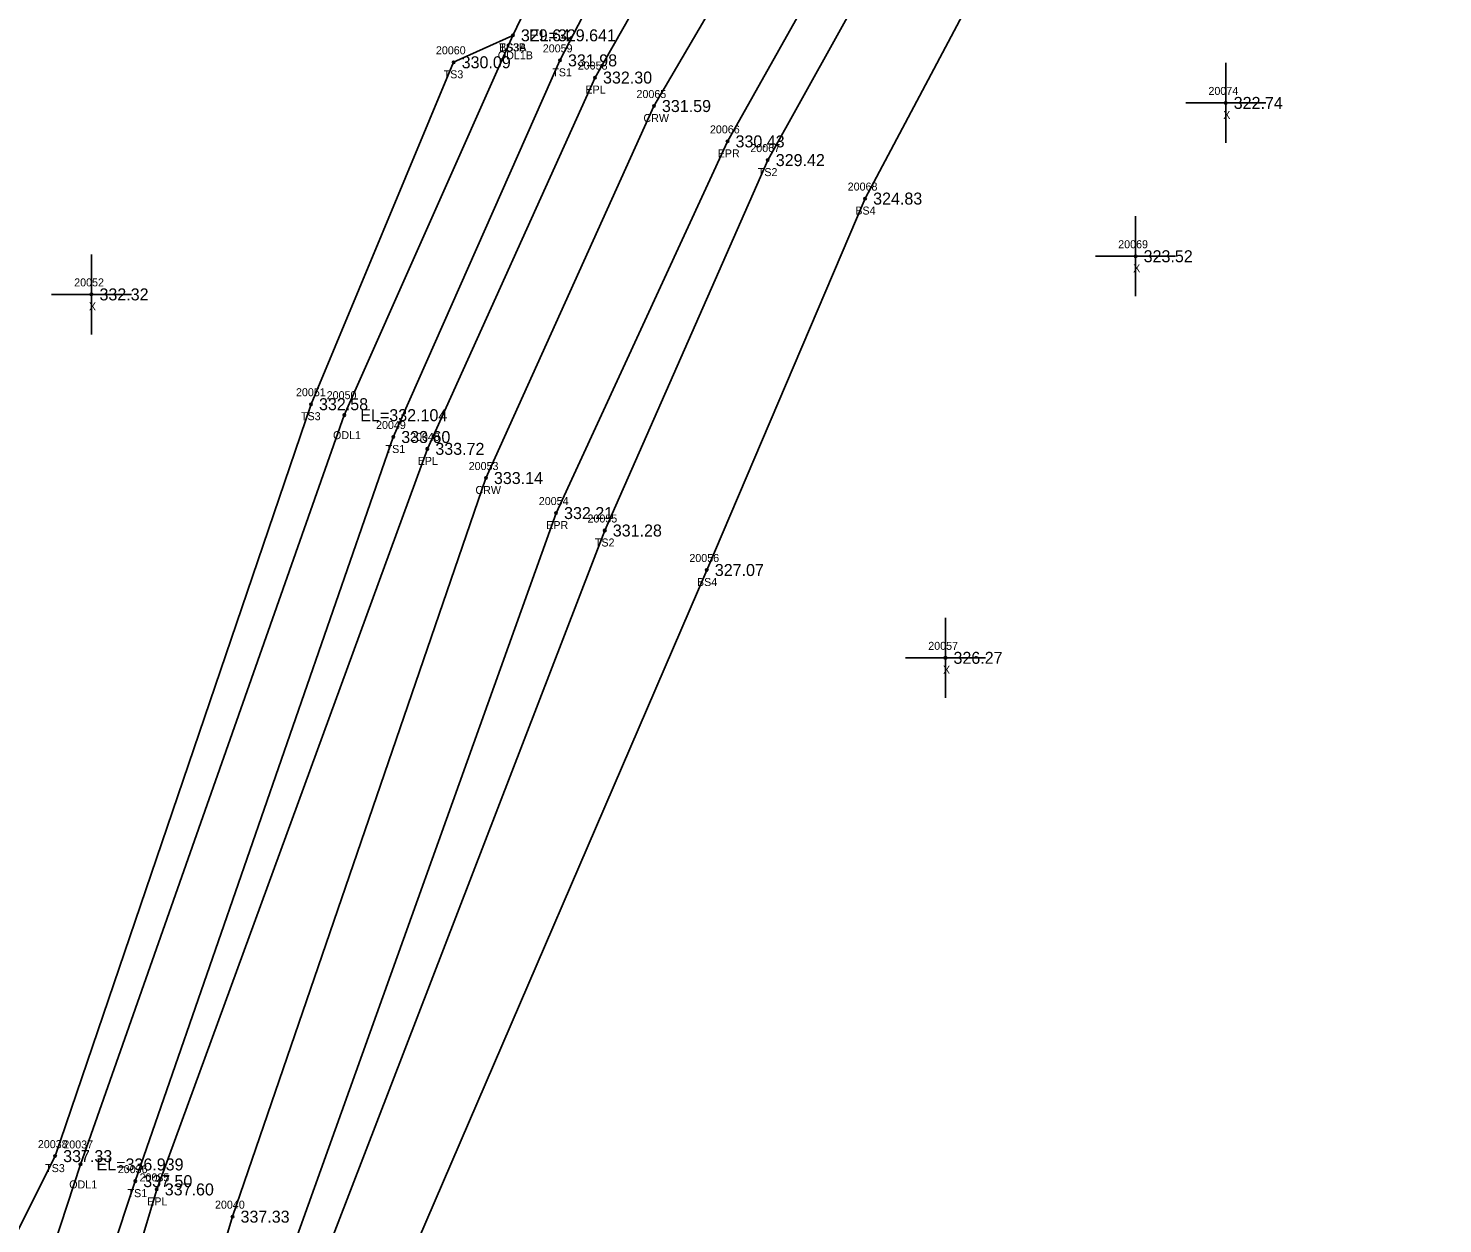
# Model space of a CAD drawing. Extents: x 2231109 to 2232328, y 1035718 to 1036919.
# Drawn here: x 2231228.7 to 2231405.5, y 1036036.4 to 1036185.9 of the extents above; entities that cross this region are included whole.
import ezdxf

# ---------------------------------------------------------------- set-up
doc = ezdxf.new("R2010")
doc.units = 0
for name, color, linetype in [('RD_DTM_BkLn1', 7, 'Continuous'), ('RD_DTM_BkLn2', 7, 'Continuous'), ('RD_DTM_BkLn_txCode', 7, 'Continuous'), ('RD_EX_H2O', 7, 'Continuous'), ('RD_EX_H2O_txCode', 7, 'Continuous'), ('RD_EX_Misc', 7, 'Continuous'), ('RD_EX_Misc_txCode', 7, 'Continuous'), ('RD_EX_Road', 7, 'Continuous'), ('RD_EX_Road_txCode', 7, 'Continuous'), ('RD_EX_TX_H2O_ELEV', 7, 'Continuous'), ('RD_EX_TX_Misc_ELEV', 7, 'Continuous'), ('RD_EX_TX_Road_ELEV', 7, 'Continuous'), ('RD_HC_Survey_ELEV', 7, 'Continuous'), ('RD_HC_Survey_txCode', 7, 'Continuous'), ('RD_SMD_Locator', 7, 'Continuous')]:
    doc.layers.add(name, color=color, linetype=linetype)

msp = doc.modelspace()

# ---------------------------------------------------------------- linework, layer by layer
at = {"layer": 'RD_DTM_BkLn1'}
msp.add_lwpolyline([(2231168.25, 1035745.18), (2231197.3, 1035848.59), (2231226.32, 1035944.04), (2231254.24, 1036037.31), (2231285.91, 1036129.66), (2231306.91, 1036176.17), (2231330.56, 1036216.58), (2231356.95, 1036257.36), (2231387.54, 1036294.26), (2231422.35, 1036330.42), (2231422.35, 1036330.4), (2231458.4, 1036362.33), (2231503.71, 1036399.67), (2231541.46, 1036424.96)], dxfattribs=at)
at = {"layer": 'RD_DTM_BkLn2'}
for points in [[(2231289.28, 1036185.01), (2231310.58, 1036229.41), (2231341.66, 1036269.31), (2231367.87, 1036310.22), (2231401.74, 1036350.83), (2231444.02, 1036383.07), (2231489.16, 1036422.11), (2231530.24, 1036446.93), (2231543.7, 1036441.83)], [(2231153.91, 1035749.54), (2231183.9, 1035852.41), (2231210.94, 1035948.08), (2231242.08, 1036041.75), (2231274.33, 1036134.79), (2231295.17, 1036181.88), (2231317.55, 1036225.12), (2231346.22, 1036265.16), (2231373.72, 1036304.6), (2231409.94, 1036342.78), (2231447.25, 1036376.56), (2231493.69, 1036413.26), (2231528.08, 1036438.61), (2231532.84, 1036438.24), (2231534.71, 1036436.33)], [(2231276.31, 1036031.77), (2231313.52, 1036118.16), (2231333.31, 1036164.6), (2231353.04, 1036201.77), (2231379.52, 1036238.63), (2231408.34, 1036274.21), (2231439.77, 1036308.83), (2231482.36, 1036339.48), (2231523.58, 1036374.84), (2231550.15, 1036393.87), (2231557.23, 1036405.65), (2231555.87, 1036413.6)], [(2231180.99, 1035741.83), (2231209.96, 1035844.49), (2231237.45, 1035939.8), (2231265.71, 1036032.03), (2231300.77, 1036123.1), (2231321.14, 1036169.41), (2231342.59, 1036208.04), (2231368.53, 1036247.79), (2231397.69, 1036285.75), (2231431.64, 1036319.41), (2231468.01, 1036352.78), (2231515.06, 1036385.58), (2231547.14, 1036404.2), (2231548.89, 1036408.2), (2231548.45, 1036412.54)], [(2231138.42, 1035755.04), (2231160.04, 1035859.88), (2231169.24, 1035891.81), (2231170.96, 1035897.04), (2231186.09, 1035952.96), (2231232.07, 1036044.88), (2231264.05, 1036138.89), (2231281.88, 1036181.64), (2231289.28, 1036185.01)]]:
    msp.add_lwpolyline(points, dxfattribs=at)
at = {"layer": 'RD_EX_H2O'}
msp.add_lwpolyline([(2231149.43, 1035751.43), (2231176.95, 1035854.91), (2231204.32, 1035949.66), (2231235.24, 1036043.84), (2231268.21, 1036137.52), (2231289.28, 1036185.01)], dxfattribs=at)
at = {"layer": 'RD_EX_Misc'}
for p, q in [((2231378.38, 1036171.56), (2231378.38, 1036181.56)), ((2231373.38, 1036176.56), (2231383.38, 1036176.56)), ((2231367.12, 1036152.39), (2231367.12, 1036162.39)), ((2231236.61, 1036147.62), (2231236.61, 1036157.62)), ((2231362.12, 1036157.39), (2231372.12, 1036157.39)), ((2231231.61, 1036152.62), (2231241.61, 1036152.62)), ((2231343.35, 1036102.18), (2231343.35, 1036112.18)), ((2231338.35, 1036107.18), (2231348.35, 1036107.18))]:
    msp.add_line(p, q, dxfattribs=at)
at = {"layer": 'RD_EX_Road'}
for points in [[(2231158.42, 1035748.11), (2231188.37, 1035851.38), (2231216.59, 1035946.92), (2231244.77, 1036040.72), (2231278.59, 1036133.31), (2231299.55, 1036179.73), (2231323.11, 1036221.2), (2231350.7, 1036262.3), (2231381.59, 1036299.29), (2231415.97, 1036336.9), (2231452.94, 1036369.74), (2231498.19, 1036405.3), (2231537.2, 1036432.57), (2231541.46, 1036424.96)], [(2231176.43, 1035742.89), (2231206.61, 1035845.83), (2231234.19, 1035940.65), (2231261.92, 1036033.75), (2231294.68, 1036125.28), (2231316.11, 1036171.75), (2231338.19, 1036211.09), (2231363.83, 1036252.38), (2231394.08, 1036289.28), (2231427.67, 1036324.2), (2231464.37, 1036355.5), (2231508.96, 1036392.41), (2231546.55, 1036416.22), (2231541.46, 1036424.96)]]:
    msp.add_lwpolyline(points, dxfattribs=at)
at = {"layer": 'RD_SMD_Locator'}
for centre in [(2231289.28, 1036185.01), (2231289.28, 1036185.01), (2231289.28, 1036185.01), (2231281.88, 1036181.64), (2231295.17, 1036181.88), (2231299.55, 1036179.73), (2231306.91, 1036176.17), (2231378.38, 1036176.56), (2231316.11, 1036171.75), (2231321.14, 1036169.41), (2231333.31, 1036164.6), (2231367.12, 1036157.39), (2231236.61, 1036152.62), (2231264.05, 1036138.89), (2231268.21, 1036137.52), (2231274.33, 1036134.79), (2231278.59, 1036133.31), (2231285.91, 1036129.66), (2231294.68, 1036125.28), (2231300.77, 1036123.1), (2231313.52, 1036118.16), (2231343.35, 1036107.18), (2231232.07, 1036044.88), (2231235.24, 1036043.84), (2231242.08, 1036041.75), (2231244.77, 1036040.72), (2231254.24, 1036037.31)]:
    msp.add_circle(centre, 0.15, dxfattribs=at)

# ---------------------------------------------------------------- texts
at = {"layer": 'RD_DTM_BkLn_txCode'}
for s, p in [('20060', (2231279.66, 1036182.64)), ('TS3B', (2231287.57, 1036183.01)), ('BS3A', (2231287.57, 1036183.01)), ('20059', (2231293.02, 1036182.88)), ('TS3', (2231280.63, 1036179.64)), ('TS1', (2231294.21, 1036179.88)), ('20067', (2231318.96, 1036170.41)), ('TS2', (2231319.89, 1036167.41)), ('20068', (2231331.13, 1036165.6)), ('BS4', (2231332.08, 1036162.6)), ('20051', (2231262.17, 1036139.89)), ('TS3', (2231262.8, 1036136.89)), ('20049', (2231272.18, 1036135.79)), ('TS1', (2231273.37, 1036132.79)), ('20055', (2231298.61, 1036124.1)), ('TS2', (2231299.53, 1036121.1)), ('20056', (2231311.34, 1036119.16)), ('BS4', (2231312.29, 1036116.16)), ('20038', (2231229.91, 1036045.88)), ('TS3', (2231230.82, 1036042.88)), ('20036', (2231239.9, 1036042.75)), ('TS1', (2231241.12, 1036039.75))]:
    msp.add_text(s, height=1, dxfattribs=at).set_placement(p)
at = {"layer": 'RD_EX_H2O_txCode'}
for s, p in [('ODL1B', (2231287.4, 1036182.01)), ('20050', (2231266.01, 1036139.52)), ('ODL1', (2231266.8, 1036134.52)), ('20037', (2231233.09, 1036045.84)), ('ODL1', (2231233.83, 1036040.84))]:
    msp.add_text(s, height=1, dxfattribs=at).set_placement(p)
at = {"layer": 'RD_EX_Misc_txCode'}
for s, p in [('20074', (2231376.22, 1036177.56)), ('X', (2231378.07, 1036174.56)), ('20069', (2231364.94, 1036158.39)), ('X', (2231366.81, 1036155.39)), ('20052', (2231234.45, 1036153.62)), ('X', (2231236.29, 1036150.62)), ('20057', (2231341.2, 1036108.18)), ('X', (2231343.04, 1036105.18))]:
    msp.add_text(s, height=1, dxfattribs=at).set_placement(p)
at = {"layer": 'RD_EX_Road_txCode'}
for s, p in [('20058', (2231297.39, 1036180.73)), ('EPL', (2231298.35, 1036177.73)), ('20066', (2231313.91, 1036172.75)), ('EPR', (2231314.88, 1036169.75)), ('20048', (2231276.43, 1036134.31)), ('EPL', (2231277.38, 1036131.31)), ('20054', (2231292.52, 1036126.28)), ('EPR', (2231293.45, 1036123.28)), ('20035', (2231242.62, 1036041.72)), ('EPL', (2231243.57, 1036038.72))]:
    msp.add_text(s, height=1, dxfattribs=at).set_placement(p)
at = {"layer": 'RD_EX_TX_H2O_ELEV'}
for s, p in [('EL=329.641', (2231291.28, 1036184.26)), ('EL=332.104', (2231270.21, 1036136.77)), ('EL=336.939', (2231237.24, 1036043.09))]:
    msp.add_text(s, height=1.5, dxfattribs=at).set_placement(p)
at = {"layer": 'RD_EX_TX_Misc_ELEV'}
for s, p in [('329.64', (2231290.28, 1036184.26)), ('329.64', (2231290.28, 1036184.26)), ('330.09', (2231282.88, 1036180.89)), ('331.98', (2231296.17, 1036181.13)), ('322.74', (2231379.38, 1036175.81)), ('329.42', (2231322.14, 1036168.66)), ('324.83', (2231334.31, 1036163.85)), ('323.52', (2231368.12, 1036156.64)), ('332.32', (2231237.61, 1036151.87)), ('332.58', (2231265.05, 1036138.14)), ('333.60', (2231275.33, 1036134.04)), ('331.28', (2231301.77, 1036122.35)), ('327.07', (2231314.52, 1036117.41)), ('326.27', (2231344.35, 1036106.43)), ('337.33', (2231233.07, 1036044.13)), ('337.50', (2231243.08, 1036041))]:
    msp.add_text(s, height=1.5, dxfattribs=at).set_placement(p)
at = {"layer": 'RD_EX_TX_Road_ELEV'}
for s, p in [('332.30', (2231300.55, 1036178.98)), ('330.43', (2231317.11, 1036171)), ('333.72', (2231279.59, 1036132.56)), ('332.21', (2231295.68, 1036124.53)), ('337.60', (2231245.77, 1036039.97))]:
    msp.add_text(s, height=1.5, dxfattribs=at).set_placement(p)
at = {"layer": 'RD_HC_Survey_ELEV'}
for s, p in [('331.59', (2231307.91, 1036175.42)), ('333.14', (2231286.91, 1036128.91)), ('337.33', (2231255.24, 1036036.56))]:
    msp.add_text(s, height=1.5, dxfattribs=at).set_placement(p)
at = {"layer": 'RD_HC_Survey_txCode'}
for s, p in [('20065', (2231304.73, 1036177.17)), ('CRW', (2231305.6, 1036174.17)), ('20053', (2231283.76, 1036130.66)), ('CRW', (2231284.6, 1036127.66)), ('20040', (2231252.05, 1036038.31))]:
    msp.add_text(s, height=1, dxfattribs=at).set_placement(p)

doc.saveas('drawing.dxf')
